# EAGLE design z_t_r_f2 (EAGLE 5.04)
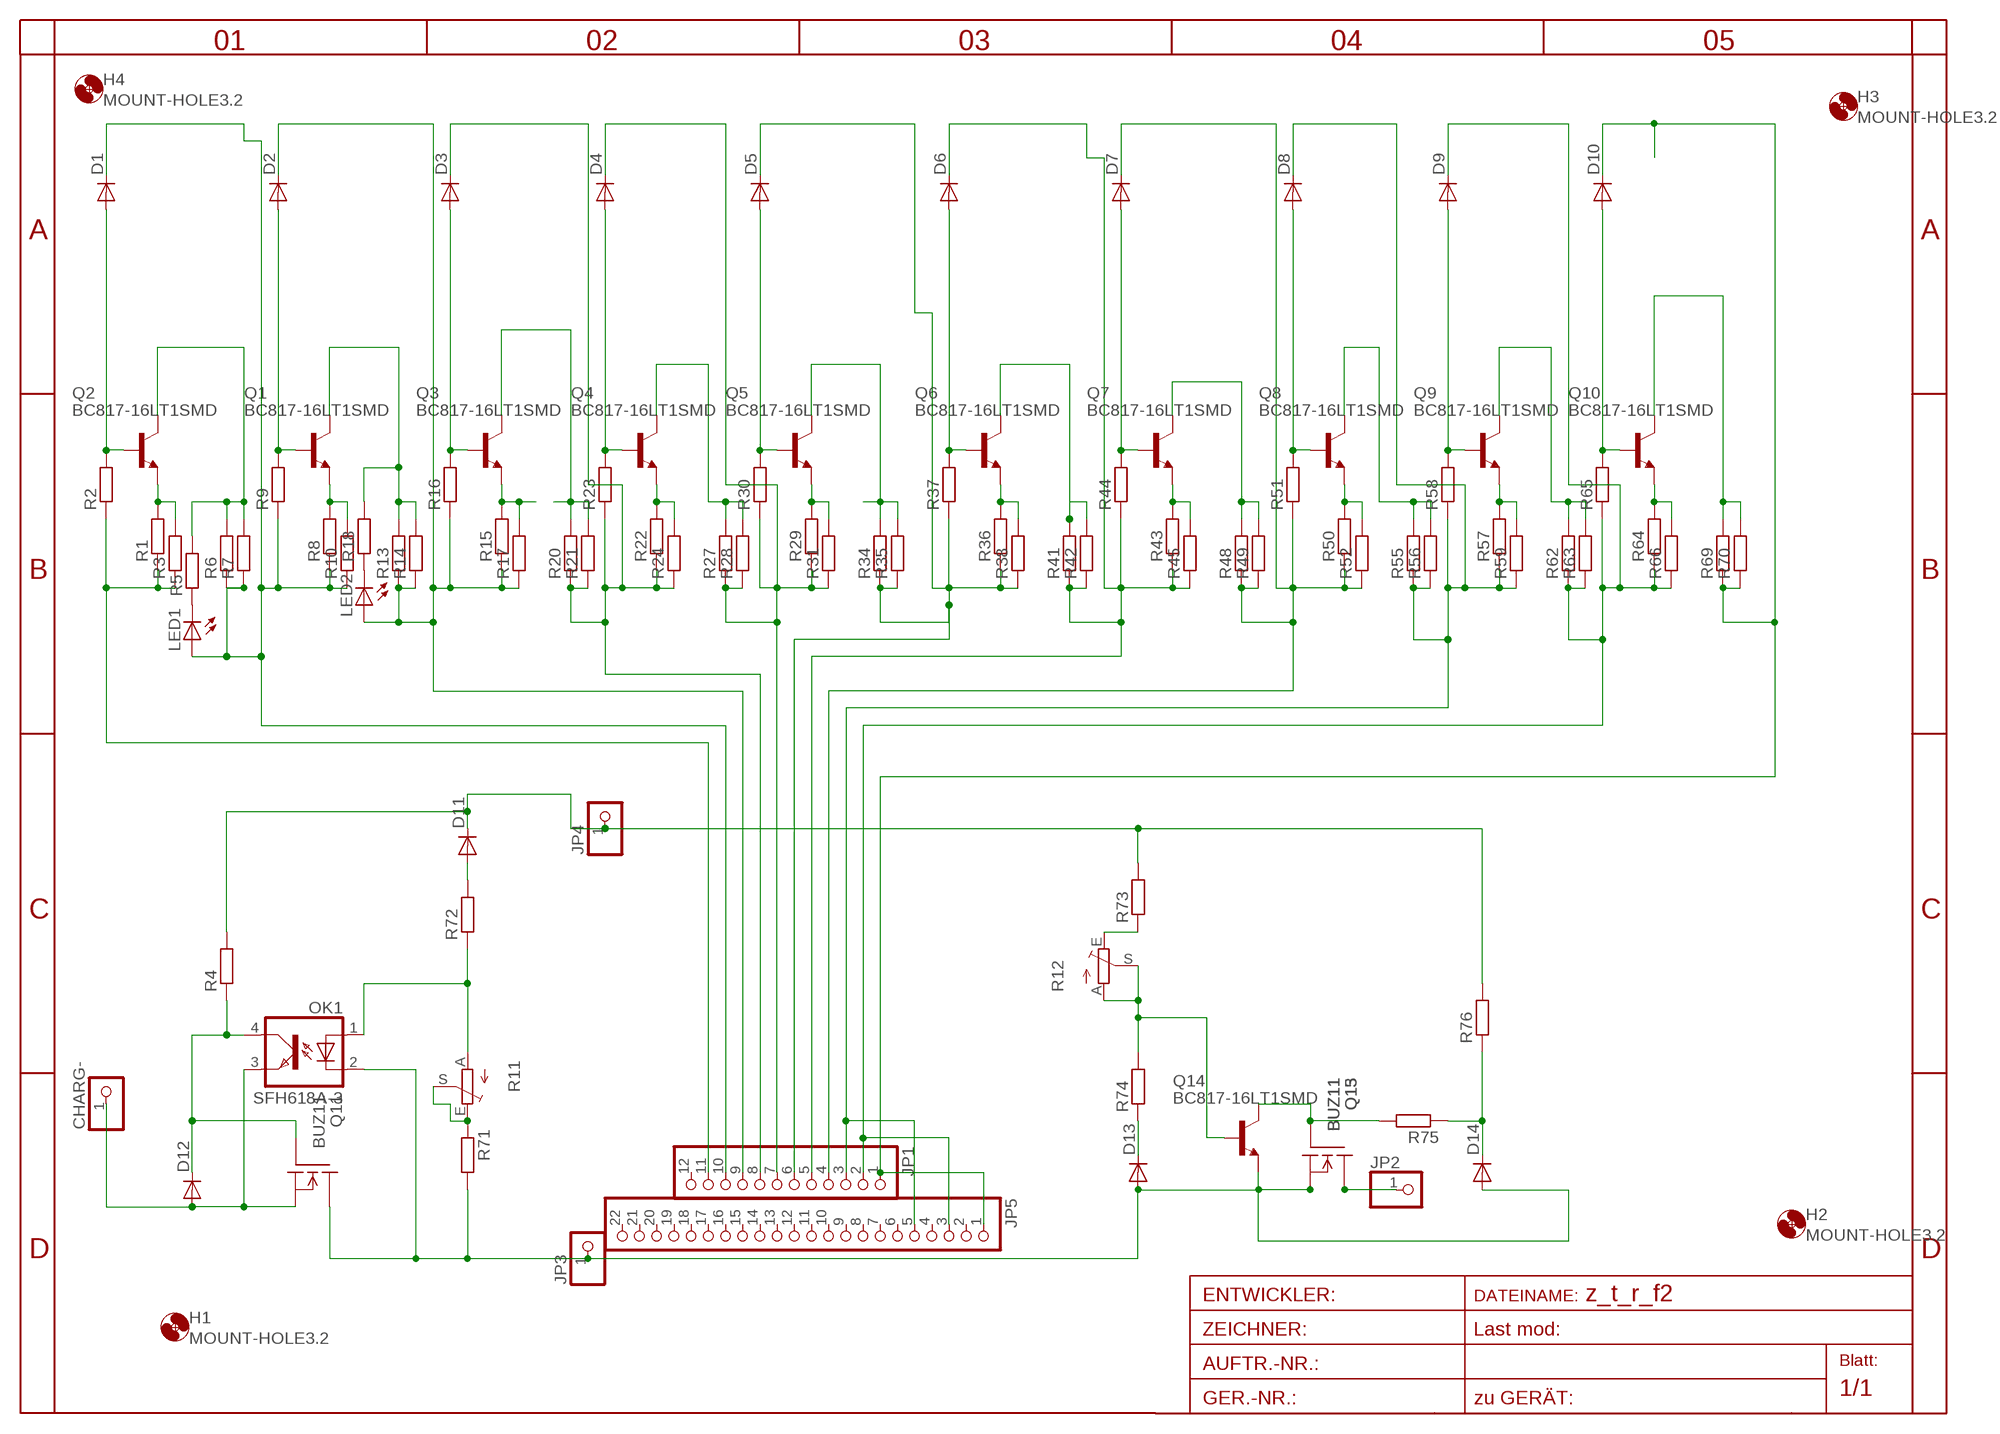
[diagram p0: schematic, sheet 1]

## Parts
CHARG-  PINHD-1X1  [1X01]
D1  DIODE-MINIMELF  [MINIMELF]
D2  DIODE-MINIMELF  [MINIMELF]
D3  DIODE-MINIMELF  [MINIMELF]
D4  DIODE-MINIMELF  [MINIMELF]
D5  DIODE-MINIMELF  [MINIMELF]
D6  DIODE-MINIMELF  [MINIMELF]
D7  DIODE-MINIMELF  [MINIMELF]
D8  DIODE-MINIMELF  [MINIMELF]
D9  DIODE-MINIMELF  [MINIMELF]
D10  DIODE-MINIMELF  [MINIMELF]
D11  DIODE-MINIMELF  [MINIMELF]
D12  DIODE-MINIMELF  [MINIMELF]
D13  DIODE-MINIMELF  [MINIMELF]
D14  DIODE-MINIMELF  [MINIMELF]
H1  MOUNT-HOLE3.2  [3,2]
H2  MOUNT-HOLE3.2  [3,2]
H3  MOUNT-HOLE3.2  [3,2]
H4  MOUNT-HOLE3.2  [3,2]
JP1  PINHD-1X12  [1X12]
JP2  PINHD-1X1  [1X01]
JP3  PINHD-1X1  [1X01]
JP4  PINHD-1X1  [1X01]
JP5  PINHD-1X22  [1X22]
LED1  LEDCHIP-LED0805  [CHIP-LED0805]
LED2  LEDCHIP-LED0805  [CHIP-LED0805]
OK1  SFH618A-3  [DIP4]
Q1  BC817-16LT1SMD  [SOT23-BEC]
Q2  BC817-16LT1SMD  [SOT23-BEC]
Q3  BC817-16LT1SMD  [SOT23-BEC]
Q4  BC817-16LT1SMD  [SOT23-BEC]
Q5  BC817-16LT1SMD  [SOT23-BEC]
Q6  BC817-16LT1SMD  [SOT23-BEC]
Q7  BC817-16LT1SMD  [SOT23-BEC]
Q8  BC817-16LT1SMD  [SOT23-BEC]
Q9  BC817-16LT1SMD  [SOT23-BEC]
Q10  BC817-16LT1SMD  [SOT23-BEC]
Q11  BUZ11  [TO220]
Q13  BUZ11  [TO220]
Q14  BC817-16LT1SMD  [SOT23-BEC]
Q15  BUZ11  [TO220]
R1  R-EU_R1206  [R1206]
R2  R-EU_R0805  [R0805]
R3  R-EU_R1206  [R1206]
R4  R-EU_R1206  [R1206]
R5  R-EU_R1206  [R1206]
R6  R-EU_R1206  [R1206]
R7  R-EU_R1206  [R1206]
R8  R-EU_R1206  [R1206]
R9  R-EU_R0805  [R0805]
R10  R-EU_R1206  [R1206]
R11  TRIM_EU-CA6V  [CA6V]
R12  TRIM_EU-CA6V  [CA6V]
R13  R-EU_R1206  [R1206]
R14  R-EU_R1206  [R1206]
R15  R-EU_R1206  [R1206]
R16  R-EU_R0805  [R0805]
R17  R-EU_R1206  [R1206]
R18  R-EU_R1206  [R1206]
R20  R-EU_R1206  [R1206]
R21  R-EU_R1206  [R1206]
R22  R-EU_R1206  [R1206]
R23  R-EU_R0805  [R0805]
R24  R-EU_R1206  [R1206]
R27  R-EU_R1206  [R1206]
R28  R-EU_R1206  [R1206]
R29  R-EU_R1206  [R1206]
R30  R-EU_R0805  [R0805]
R31  R-EU_R1206  [R1206]
R34  R-EU_R1206  [R1206]
R35  R-EU_R1206  [R1206]
R36  R-EU_R1206  [R1206]
R37  R-EU_R0805  [R0805]
R38  R-EU_R1206  [R1206]
R41  R-EU_R1206  [R1206]
R42  R-EU_R1206  [R1206]
R43  R-EU_R1206  [R1206]
R44  R-EU_R0805  [R0805]
R45  R-EU_R1206  [R1206]
R48  R-EU_R1206  [R1206]
R49  R-EU_R1206  [R1206]
R50  R-EU_R1206  [R1206]
R51  R-EU_R0805  [R0805]
R52  R-EU_R1206  [R1206]
R55  R-EU_R1206  [R1206]
R56  R-EU_R1206  [R1206]
R57  R-EU_R1206  [R1206]
R58  R-EU_R0805  [R0805]
R59  R-EU_R1206  [R1206]
R62  R-EU_R1206  [R1206]
R63  R-EU_R1206  [R1206]
R64  R-EU_R1206  [R1206]
R65  R-EU_R0805  [R0805]
R66  R-EU_R1206  [R1206]
R69  R-EU_R1206  [R1206]
R70  R-EU_R1206  [R1206]
R71  R-EU_R1206  [R1206]
R72  R-EU_R1206  [R1206]
R73  R-EU_R1206  [R1206]
R74  R-EU_R1206  [R1206]
R75  R-EU_R1206  [R1206]
R76  R-EU_R1206  [R1206]

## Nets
B1: D1.C JP1.10 LED1.A R6.1 R7.1 R8.1 R9.1 R10.1
B2: D2.C JP1.9 LED2.A R13.1 R14.1 R15.1 R16.1 R17.1
B3: D3.C JP1.8 R20.1 R21.1 R22.1 R23.1 R24.1
B4: D4.C JP1.7 R27.1 R28.1 R29.1 R30.1 R31.1
B5: D5.C JP1.6 R34.1 R35.1 R36.1 R37.1 R38.1
B6: D6.C JP1.5 R41.1 R42.1 R43.1 R44.1 R45.1
B7: D7.C JP1.4 R48.1 R49.1 R50.1 R51.1 R52.1
B8: D8.C JP1.3 JP5.5 R55.1 R56.1 R57.1 R58.1 R59.1
B9: D9.C JP1.2 JP5.3 R62.1 R63.1 R64.1 R65.1 R66.1
B10: D10.C JP1.1 JP5.1 R69.1 R70.1
B-: JP1.11 R1.1 R2.1 R3.1
BATT+: D11.C JP4.1 R4.2 R73.2 R76.2
BATT-: D13.A D14.A JP3.1 OK1.2(C) Q11.2(D) Q13.3(S) Q14.E Q15.3(S) R71.2
CHAR-: CHARG-.1 D12.A OK1.3(EMIT) Q11.3(S)
D0: D1.A Q2.B R2.2
D1: D2.A Q1.B R9.2
D2: D3.A Q3.B R16.2
D3: D4.A Q4.B R23.2
D4: D5.A Q5.B R30.2
D5: D6.A Q6.B R37.2
D6: D7.A Q7.B R44.2
D7: D8.A Q8.B R51.2
D8: D9.A Q9.B R58.2
D9: D10.A Q10.B R65.2
MOTOR-: JP2.1 Q13.2(D) Q15.2(D)
N$1: Q2.C R5.2 R6.2 R7.2
N$2: Q2.E R1.2 R3.2
N$3: Q1.C R13.2 R14.2 R18.2
N$4: Q1.E R8.2 R10.2
N$5: OK1.1(A) R11.A R72.1
N$6: Q3.C R20.2 R21.2
N$7: R11.E R11.S R71.1
N$8: Q4.E R22.2 R24.2
N$9: R12.E R73.1
N$10: Q5.C R34.2 R35.2
N$11: D12.C OK1.4(COL) Q11.1(G) R4.1
N$12: Q6.C R41.2 R42.2
N$13: Q14.B R12.A R12.S R74.2
N$14: Q7.E R43.2 R45.2
N$15: D13.C R74.1
N$16: Q8.C R55.2 R56.2
N$17: LED1.C R5.1
N$18: Q9.E R57.2 R59.2
N$20: Q10.C R69.2 R70.2
N$21: D11.A R72.2
N$23: Q5.E R29.2 R31.2
N$24: Q3.E R15.2 R17.2
N$25: Q13.1(G) Q14.C Q15.1(G) R75.2
N$26: LED2.C R18.1
N$27: D14.C R75.1 R76.1
N$29: Q4.C R27.2 R28.2
N$31: Q6.E R36.2 R38.2
N$33: Q7.C R48.2 R49.2
N$36: Q8.E R50.2 R52.2
N$37: Q9.C R62.2 R63.2
N$40: Q10.E R64.2 R66.2
Unconnected: JP1.12 JP5.2 JP5.4 JP5.6 JP5.7 JP5.8 JP5.9 JP5.10 JP5.11 JP5.12 JP5.13 JP5.14 JP5.15 JP5.16 JP5.17 JP5.18 JP5.19 JP5.20 JP5.21 JP5.22

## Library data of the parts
CHARG- JP2-JP4 = pinhead:PINHD-1X1: PIN HEADER
D1-D14 = diode-1:DIODE-: DIODE
H1-H4 = holes:MOUNT-HOLE: MOUNTING HOLE with drill center marker
JP1 = pinhead:PINHD-1X12: PIN HEADER
JP5 = pinhead:PINHD-1X22: PIN HEADER
LED1 LED2 = led:LED: LED
OK1 = optocoupler:SFH618?*: Optocoupler, Phototransistor Output, Low Input Current Source: http://www.vishay.com/docs/83673/sfh618.pdf
Q1-Q10 Q14 = transistor-npn:BC817*: NPN Transistor
Q11 Q13 Q15 = transistor-fet:BUZ11: N-Channel Enhancement MOSFET 50V; 30A; 0,040Ohm
R1-R10 R13-R18 R20-R24 R27-R31 R34-R38 R41-R45 R48-R52 R55-R59 R62-R66 R69-R76 = rcl-2:R-EU_: RESISTOR, European symbol
R11 R12 = pot:TRIM_EU-: POTENTIOMETER

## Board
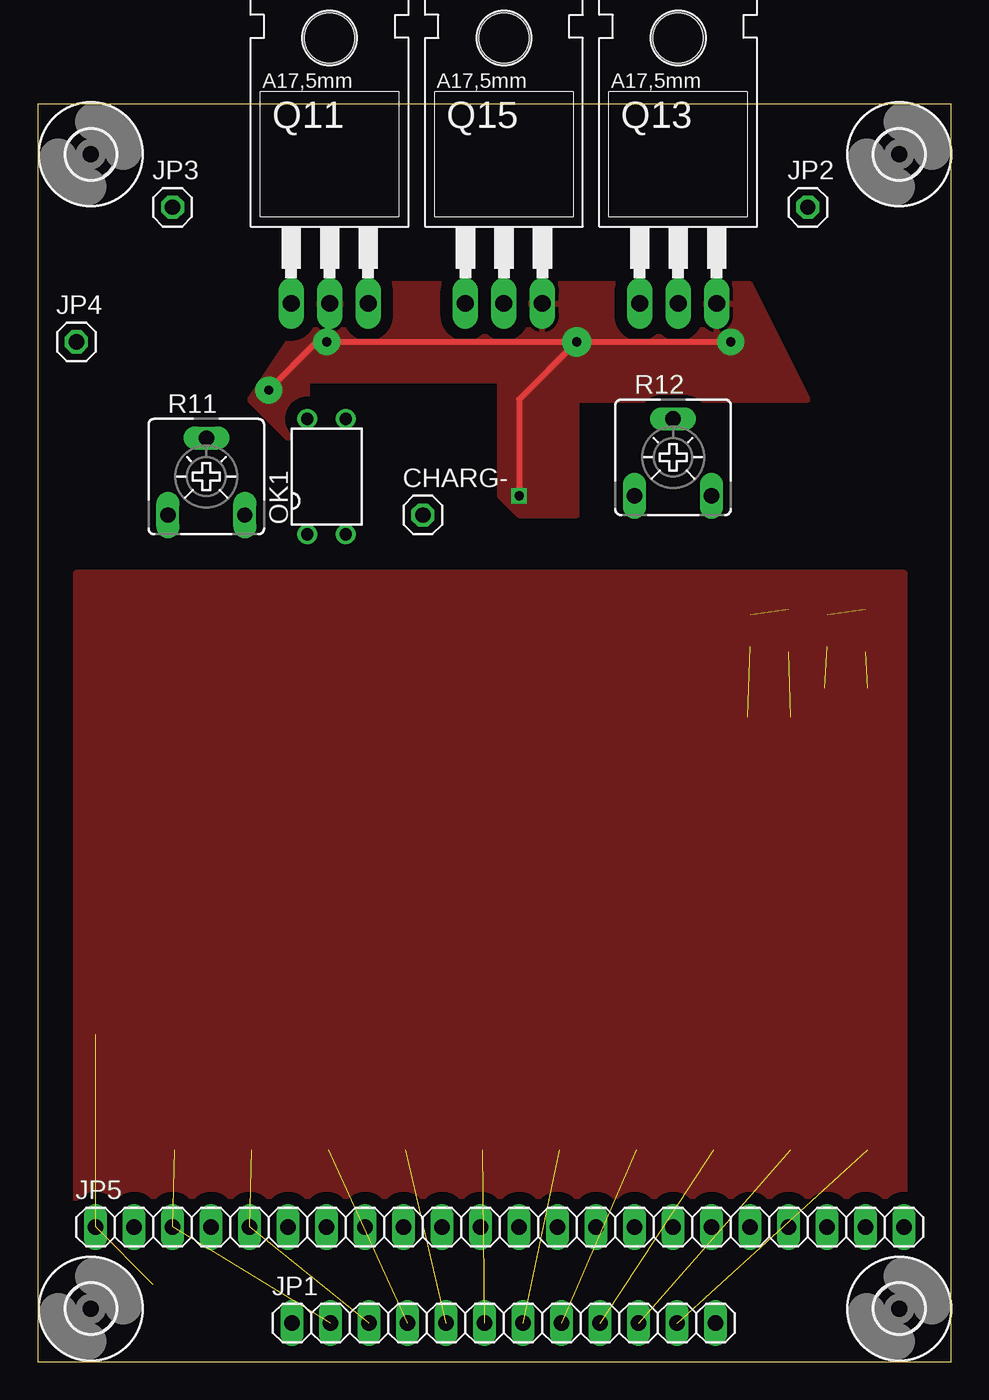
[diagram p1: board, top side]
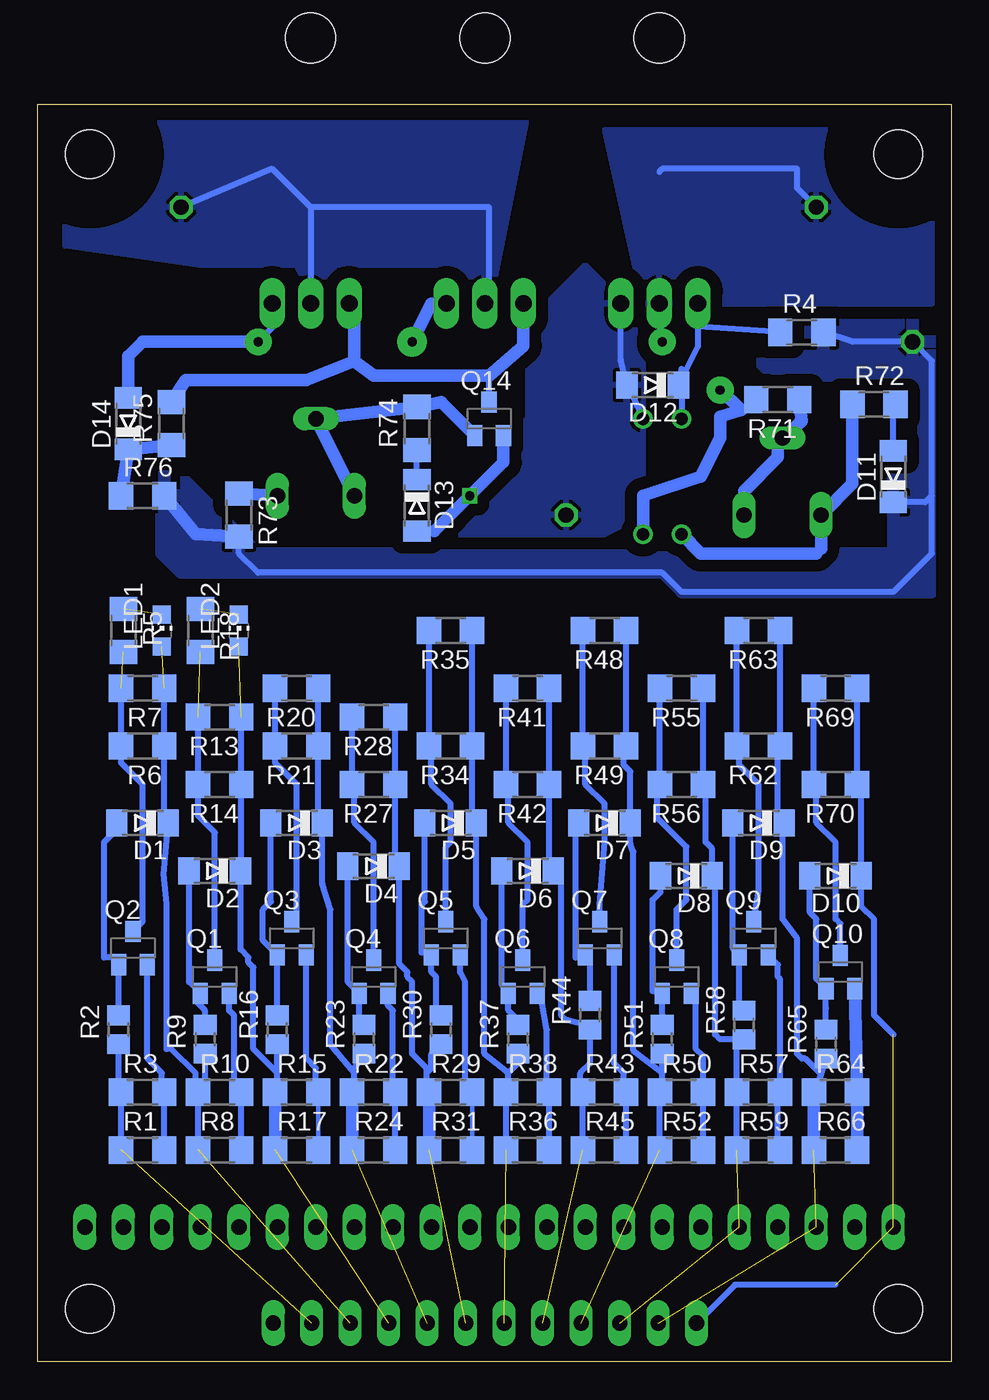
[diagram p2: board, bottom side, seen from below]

Size 60.25 x 83 mm. Coordinates in mm from the lower left corner, seen from the top.
Outline: 0,0 60.25,0 60.25,83 0,83 0,0
Copper layers (1*16): Top 0.035mm / dielectric 1.5mm / Bottom 0.035mm
Design rules "default": minimum track width 10mil, minimum drill 24mil, track to track 8mil, track to pad 8mil, pad to pad 8mil, via to via 8mil, smd to smd 8mil, copper to edge 40mil, drill to drill 8mil, minimum pad ring 10mil, minimum via ring 8mil, stop-mask expansion 4mil, vias tented up to drill 0mil, thermal gap 10mil

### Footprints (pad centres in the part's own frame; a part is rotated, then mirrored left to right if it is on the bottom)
1X01 = drill 1.016 octagon: 1 0,0
MINIMELF = smd 1.4 x 1.8: A 1.7,0; C -1.7,0
3,2 = hole 3.2: 0,0
1X12 = drill 1.016 long: 1 -13.97,0; 2 -11.43,0; 3 -8.89,0; 4 -6.35,0; 5 -3.81,0; 6 -1.27,0; 7 1.27,0; 8 3.81,0; 9 6.35,0; 10 8.89,0; 11 11.43,0; 12 13.97,0
1X22 = drill 1.016 long: 1 -26.67,0; 2 -24.13,0; 3 -21.59,0; 4 -19.05,0; 5 -16.51,0; 6 -13.97,0; 7 -11.43,0; 8 -8.89,0; 9 -6.35,0; 10 -3.81,0; 11 -1.27,0; 12 1.27,0; 13 3.81,0; 14 6.35,0; 15 8.89,0; 16 11.43,0; 17 13.97,0; 18 16.51,0; 19 19.05,0; 20 21.59,0; 21 24.13,0; 22 26.67,0
CHIP-LED0805 = smd 1.2 x 1.2: A 0,-1.05; C 0,1.05
DIP4 = drill 0.8 round: 1 -1.27,-3.81; 2 1.27,-3.81; 3 1.27,3.81; 4 -1.27,3.81
SOT23-BEC = smd 1 x 1.4: B -0.95,-1.1; C 0,1.1; E 0.95,-1.1
TO220 = drill 1.118 long: 1 -2.54,-6.35; 2 0,-6.35; 3 2.54,-6.35 | hole 3.302: 0,11.176
R1206 = smd 1.6 x 1.803: 1 -1.422,0; 2 1.422,0
R0805 = smd 1.3 x 1.5: 1 -0.95,0; 2 0.95,0
CA6V = drill 1.016 long: A -2.54,-2.54; E 2.54,-2.54; S 0,2.54

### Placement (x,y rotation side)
CHARG-  25.4,55.88 0 top
D1  53.34,35.56 180 bottom
D2  48.58,32.38 180 bottom
D3  43.18,35.56 180 bottom
D4  38.1,32.7 180 bottom
D5  33.02,35.56 180 bottom
D6  27.94,32.38 180 bottom
D7  22.86,35.56 180 bottom
D8  17.46,32.07 180 bottom
D9  12.7,35.56 180 bottom
D10  7.62,32.07 180 bottom
D11  3.81,58.42 90 bottom
D12  19.68,64.45 180 bottom
D13  35.24,56.52 270 bottom
D14  54.29,61.91 90 bottom
H1  3.49,79.69 0 top
H2  56.83,79.69 0 top
H3  3.49,3.49 0 top
H4  56.83,3.49 0 top
JP1  30.75,2.54 0 top
JP2  50.8,76.2 0 top
JP3  8.89,76.2 0 top
JP4  2.54,67.31 0 top
JP5  30.48,8.89 0 top
LED1  52.07,48.26 0 bottom
LED2  46.99,48.26 0 bottom
OK1  19.05,58.42 0 top
Q1  48.58,25.4 0 bottom
Q2  53.98,27.3 0 bottom
Q3  43.5,27.94 0 bottom
Q4  38.1,25.4 0 bottom
Q5  33.34,27.94 0 bottom
Q6  28.26,25.4 0 bottom
Q7  23.18,27.94 0 bottom
Q8  18.1,25.4 0 bottom
Q9  13.02,27.94 0 bottom
Q10  7.3,25.72 0 bottom
Q11  19.25,76.2 0 top
Q13  42.25,76.2 0 top
Q14  30.48,62.23 0 bottom
Q15  30.75,76.2 0 top
R1  53.34,13.97 0 bottom
R2  54.93,21.91 90 bottom
R3  53.34,17.78 0 bottom
R4  9.84,67.94 0 bottom
R5  54.61,48.26 270 bottom
R6  53.34,40.64 180 bottom
R7  53.34,44.45 180 bottom
R8  48.26,13.97 0 bottom
R9  49.21,21.27 90 bottom
R10  48.26,17.78 0 bottom
R11  11.11,58.42 0 top
R12  41.91,59.69 0 top
R13  48.26,42.55 180 bottom
R14  48.26,38.1 180 bottom
R15  43.18,17.78 0 bottom
R16  44.45,21.91 90 bottom
R17  43.18,13.97 0 bottom
R18  49.53,48.26 270 bottom
R20  43.18,44.45 180 bottom
R21  43.18,40.64 180 bottom
R22  38.1,17.78 0 bottom
R23  38.73,21.27 90 bottom
R24  38.1,13.97 0 bottom
R27  38.1,38.1 180 bottom
R28  38.1,42.55 180 bottom
R29  33.02,17.78 0 bottom
R30  33.66,21.91 90 bottom
R31  33.02,13.97 0 bottom
R34  33.02,40.64 180 bottom
R35  33.02,48.26 180 bottom
R36  27.94,13.97 0 bottom
R37  28.57,21.27 90 bottom
R38  27.94,17.78 0 bottom
R41  27.94,44.45 180 bottom
R42  27.94,38.1 180 bottom
R43  22.86,17.78 0 bottom
R44  23.81,22.86 90 bottom
R45  22.86,13.97 0 bottom
R48  22.86,48.26 180 bottom
R49  22.86,40.64 180 bottom
R50  17.78,17.78 0 bottom
R51  19.05,21.27 90 bottom
R52  17.78,13.97 0 bottom
R55  17.78,44.45 180 bottom
R56  17.78,38.1 180 bottom
R57  12.7,17.78 0 bottom
R58  13.65,22.23 90 bottom
R59  12.7,13.97 0 bottom
R62  12.7,40.64 180 bottom
R63  12.7,48.26 180 bottom
R64  7.62,17.78 0 bottom
R65  8.26,20.95 90 bottom
R66  7.62,13.97 0 bottom
R69  7.62,44.45 180 bottom
R70  7.62,38.1 180 bottom
R71  11.43,63.5 180 bottom
R72  5.08,63.18 0 bottom
R73  46.99,55.88 270 bottom
R74  35.24,61.59 90 bottom
R75  51.44,61.91 90 bottom
R76  53.34,57.15 0 bottom

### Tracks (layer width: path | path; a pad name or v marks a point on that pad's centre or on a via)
B1  (2 unrouted)
  Bottom 0.406: R7.1 51.92,40.79 52.07,40.64 R6.1 51.92,35.84 D1.C 51.96,32.18 51.75,30.16 51.75,20.64 51.44,20.64 49.85,19.05 49.85,18.41 49.68,18.25 R10.1 | R9.1 49.21,18.25 R10.1 | R8.1 R10.1
B2  (2 unrouted)
  Bottom 0.406: R13.1 R14.1 46.84,32.42 D2.C 46.88,27.19 46.35,26.67 46.35,26.35 46.04,26.04 46.04,20.64 44.45,19.05 | 44.45,19.05 44.45,17.93 R15.1 | 44.45,19.05 R16.1
  Bottom 0.813: R17.1 R15.1
B3  (1 unrouted)
  Bottom 0.406: 39.55,19.27 39.37,19.05 39.37,17.93 R22.1 | 39.55,19.27 40.96,20.95 40.96,29.84 41.48,31.55 D3.C 41.76,35.84 R21.1 R20.1 | R23.1 38.73,20.09 39.55,19.27
  Bottom 0.813: R24.1 R22.1
B4  (1 unrouted)
  Bottom 0.406: R28.1 R27.1 36.68,32.98 D4.C 36.4,26.24 35.88,25.72 35.88,25.4 35.56,25.08 35.56,20.32 34.61,19.37 34.61,19.05 | 34.61,19.05 34.61,17.95 R29.1 | R30.1 34.29,20.32 34.29,19.37 34.61,19.05
  Bottom 0.813: R31.1 R29.1
B5  (1 unrouted)
  Bottom 0.406: 29.21,19.05 30.8,20.32 30.8,29.21 31.32,30.05 D5.C 31.6,35.84 R34.1 R35.1 | 29.21,19.05 29.21,17.93 R38.1 R36.1 | R37.1 28.57,19.68 29.21,19.05
B6  (1 unrouted)
  Bottom 0.406: R41.1 R42.1 26.52,32.66 D6.C 25.72,32.38 25.72,22.86 25.4,22.54 24.13,22.23 R44.1 23.81,19.68 24.45,19.05 24.45,17.95 R43.1 R45.1
B7  (1 unrouted)
  Bottom 0.406: 19.05,19.05 R51.1 | 19.05,19.05 19.05,17.93 R50.1 R52.1 | 19.05,19.05 20.95,20.52 20.95,33.66 21.16,34.18 D7.C 21.16,38.94 21.59,39.37 21.59,40.49 R49.1 R48.1
B8  (2 unrouted)
  Bottom 0.406: R55.1 R56.1 16.19,37.93 16.19,34.29 15.76,33.86 D8.C 15.56,31.64 15.56,21.59 15.24,21.27 R58.1 14.12,21.12 R57.1 R59.1
B9  (2 unrouted)
  Bottom 0.406: 8.58,18.95 8.89,17.93 R64.1 | 8.58,18.95 R65.1 | 11.43,48.26 R63.1 R62.1 11.43,40.49 11.43,35.56 D9.C 11.11,35.13 11.11,29.21 10.16,27.94 10.16,20.32 9.85,20 9.63,20 8.58,18.95
  Bottom 0.813: R66.1 R64.1
B10  (2 unrouted)
  Bottom 0.406: R69.1 R70.1 5.92,37.82 D10.C 5.92,30.05 5.08,29.21 5.08,22.86 3.81,21.59 | 7.62,5.08 14.24,5.08 JP1.1
B-  (1 unrouted)
  Bottom 0.406: R2.1 54.93,17.95 R3.1 R1.1
BATT+
  Bottom 0.406: D11.C 1.7,56.72 1.27,57.15 | 1.27,57.15 1.27,66.04 JP4.1 6.52,67.31 R4.2 | R73.2 46.99,53.34 45.72,52.07 19.05,52.07 17.78,50.8 3.81,50.8 1.27,53.34 1.27,57.15
  Bottom 0.813: R76.2 49.85,54.61 R73.2
  pour Bottom (isolate 0.813, rank 3): 1.27,69.85 10.16,69.85 12.7,67.31 12.7,66.04 10.16,63.5 3.81,63.5 3.81,53.34 45.72,53.34 50.8,58.42 52.07,58.42 52.07,53.34 50.8,52.07 19.05,52.07 17.78,50.8 1.27,50.8
BATT-  (via drill 0.6, 0.6 pad 1.78, 0.6 pad 1.93)
  Top 0.406: v35.56,67.31 v19.05,67.31 18.41,67.31 v15.24,64.14 | v35.56,67.31 v45.72,67.31 | v31.75,57.15 31.75,63.5 v35.56,67.31
  Bottom 0.406: 19.25,78.54 19.05,78.74 10.16,78.74 10.16,77.47 JP3.1 | 13.86,62.8 R71.2 | 15.18,64.14 v15.24,64.14 | Q11.2 19.25,68.78 v19.05,67.31 | Q13.3 44.79,68.24 v45.72,67.31 | 34.09,54.81 D13.A
  Bottom 0.813: Q15.3 34.29,69.85 v35.56,67.31 | OK1.2 20.32,57.15 16.51,58.42 15.24,60.96 15.24,62.38 13.86,62.8 15.18,64.14 | D14.A 54.29,66.36 53.34,67.31 v45.72,67.31 | 34.09,54.81 v31.75,57.15 29.53,59.37 Q14.E
  pour Bottom (isolate 0.813, rank 2): 1.27,81.28 22.86,81.28 20.32,69.85 1.27,69.85
  pour Top (isolate 0.813, rank 2): 19.05,71.12 13.97,63.5 16.51,60.96 17.78,62.23 17.78,64.77 30.48,64.77 30.48,57.15 31.75,55.88 35.56,55.88 35.56,63.5 50.8,63.5 46.99,71.12
CHAR-
  Bottom 0.406: Q11.3 21.79,66.13 D12.A 21.39,64.56 OK1.3
  pour Bottom (isolate 0.813): 20.32,68.58 24.13,72.39 27.94,68.58 27.94,62.23 33.02,57.15 33.02,54.61 22.86,54.61 20.32,55.88
D0
  Bottom 0.406: R2.2 Q2.B 55.39,26.67 55.88,26.67 55.88,34.29 55.04,35.13 D1.A
D1
  Bottom 0.406: R9.2 49.21,23.18 49.85,23.81 49.85,23.98 Q1.B 50.28,25.05 D2.A
D2
  Bottom 0.406: D3.A 44.88,30.37 45.4,29.84 45.4,27.8 Q3.B R16.2
D3
  Bottom 0.406: D4.A 39.8,25.05 Q4.B 39.05,22.54 R23.2
D4
  Bottom 0.406: D5.A 34.72,30.37 34.92,30.16 34.92,26.99 34.44,26.99 Q5.B 34.29,25.71 33.97,25.4 33.97,23.18 R30.2
D5
  Bottom 0.406: R37.2 28.57,22.54 29.21,23.18 Q6.B 29.53,24.62 29.53,24.77 29.64,24.88 D6.A
D6
  Bottom 0.406: D7.A 24.77,35.56 24.77,26.67 24.13,26.67 Q7.B 23.81,26.84 R44.2
D7
  Bottom 0.406: D8.A 19.16,31 19.68,30.48 19.68,24.45 19.2,24.45 Q8.B 19.05,22.86 R51.2
D8
  Bottom 0.406: R58.2 13.97,23.18 Q9.B 14.4,27.27 D9.A
D9
  Bottom 0.406: R65.2 8.26,23.34 Q10.B 8.89,25.25 8.89,29.21 9.32,29.64 D10.A
MOTOR-
  Bottom 0.406: Q15.2 30.48,69.85 30.48,76.2 42.25,76.2 | 42.25,76.2 Q13.2 | JP2.1 44.79,78.74 42.25,76.2
  pour Bottom (isolate 0.813): 58.42,73.66 58.42,82.55 27.94,82.55 30.48,69.85 33.02,72.39 40.64,72.39 41.91,69.85 43.18,72.39 49.53,72.39
N$1  (1 unrouted)
  Bottom 0.406: R7.2 R6.2 54.76,39.52 53.34,38.1 53.34,29.04 Q2.C
N$2
  Bottom 0.406: Q2.E 53.02,20 52.07,19.05 52.07,17.93 R3.2 R1.2
N$3  (1 unrouted)
  Bottom 0.406: R13.2 R14.2 49.68,36.03 48.58,34.92 Q1.C
N$4
  Bottom 0.406: Q1.E 47.63,23.18 47.31,22.86 47.31,18.1 47.16,18.1 R10.2 46.84,14.12 46.99,13.97 R8.2
N$5
  Bottom 0.406: 8.57,53.66 8.89,53.34
  Bottom 0.813: 8.57,53.66 R11.A 6.5,57.95 R72.1 | 8.89,53.34 16.51,53.34 OK1.1
N$6
  Bottom 0.406: R20.2 44.6,40.79 44.45,40.64 R21.2 44.6,39.52 43.18,38.1 43.18,29.21 43.33,29.21 Q3.C
N$7
  Bottom 0.406: 11.43,60.64 R11.S
  Bottom 0.813: R11.E 13.65,57.47 11.43,59.69 11.43,60.64 | R11.S 9.84,62.06 R71.1
N$8
  Bottom 0.406: Q4.E 37.15,23.5 36.83,23.18 36.83,17.93 R22.2 R24.2
N$9
  Bottom 0.813: R12.E R73.1
N$10
  Bottom 0.406: R35.2 R34.2 34.29,40.49 34.29,38.1 33.02,36.83 33.02,34.29 33.34,33.97 Q5.C
N$11
  Bottom 0.406: 16.71,68.31 16.71,67 D12.C 17.78,65.52 OK1.4 | 16.71,68.31 Q11.1 | R4.1 16.71,68.31
N$12
  Bottom 0.406: Q6.C 28.26,30.16 27.94,30.48 27.94,34.29 29.21,35.56 29.21,37.95 R42.2 R41.2
N$13
  Bottom 0.813: Q14.B 33.63,63.33 R74.2 R12.S R12.A
N$14
  Bottom 0.406: Q7.E 22.23,19.69 21.59,19.05 21.59,17.93 R43.2 R45.2
N$15
  Bottom 0.406: D13.C R74.1
N$16
  Bottom 0.406: Q8.C 18.1,29.84 17.46,30.48 17.46,33.97 19.37,35.88 19.37,37.93 R56.2 R55.2
N$17  (1 unrouted)
N$18
  Bottom 0.406: Q9.E 11.43,26.2 11.43,25.4 11.28,25.25 R57.2 11.43,17.78 11.43,14.12 R59.2
N$20
  Bottom 0.406: R69.2 R70.2 8.89,37.95 8.89,35.56 7.62,34.29 7.62,29.21 7.3,28.89 Q10.C
N$21
  Bottom 0.406: D11.A 3.81,63.03 R72.2
N$22
  pour Top (isolate 0.813, rank 2): 2.54,52.07 57.15,52.07 57.15,7.62 2.54,7.62
N$23
  Bottom 0.305: R31.2 R29.2
  Bottom 0.406: Q5.E 32.39,25.72 32.07,25.08 32.07,17.93 R29.2
N$24
  Bottom 0.305: R17.2 R15.2
  Bottom 0.406: Q3.E 42.55,20 41.91,19.37 41.91,17.93 R15.2
N$25
  Bottom 0.406: Q14.C 30.48,65.09
  Bottom 0.813: Q15.1 28.21,67.04 30.48,65.09 38.1,65.09 39.37,66.04 | 39.37,66.04 39.37,69.51 Q13.1 | 39.37,66.04 42.55,64.77 50.48,64.77 R75.2
N$26  (1 unrouted)
N$27
  Bottom 0.813: R76.1 D14.C R75.1
N$29
  Bottom 0.406: R28.2 R27.2 39.37,37.95 39.37,35.56 38.1,34.29 Q4.C
N$31
  Bottom 0.406: Q6.E 26.99,23.82 26.67,21.91 26.67,17.93 R38.2 R36.2
N$33
  Bottom 0.406: Q7.C 23.18,30.16 22.86,34.29 22.86,36.83 24.13,38.1 24.13,40.49 R49.2 R48.2
N$36
  Bottom 0.406: Q8.E 16.83,23.98 16.83,20.64 16.36,20.17 R50.2 R52.2
N$37
  Bottom 0.406: Q9.C 12.7,31.11 12.7,38.1 13.97,39.37 13.97,40.49 R62.2 R63.2
N$40
  Bottom 0.813: Q10.E R64.2 R66.2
